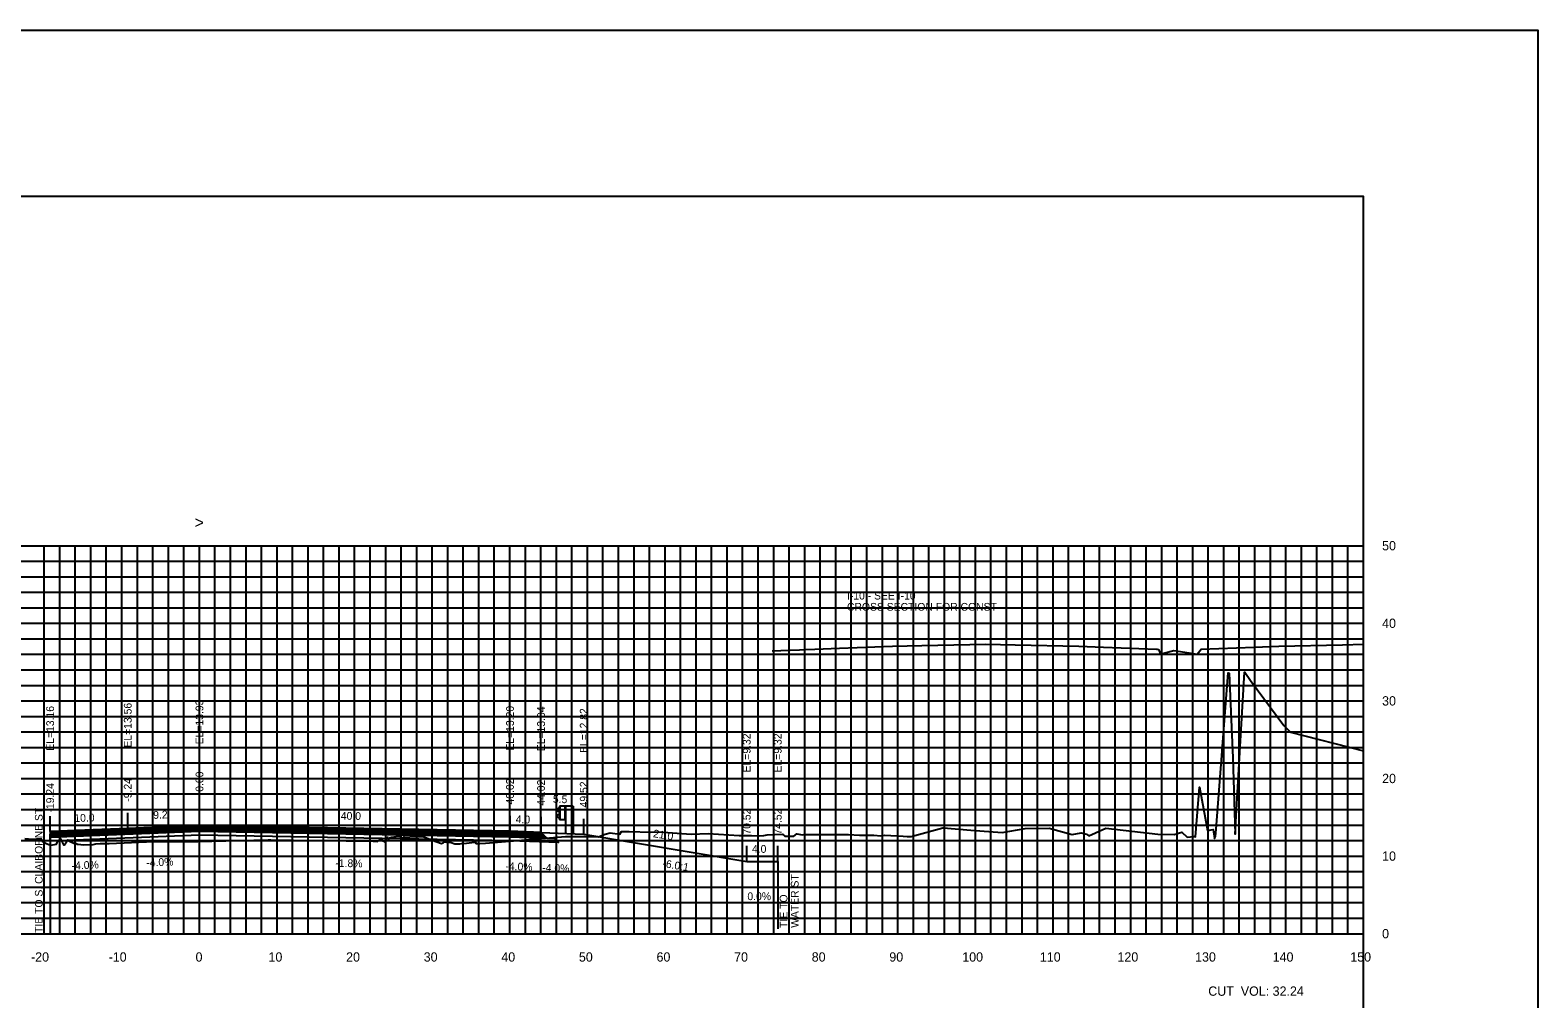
# Model space of a CAD drawing. Extents: x 1797518 to 1804843, y 248068 to 251132.
# Drawn here: x 1804649.2 to 1804843.5, y 250166 to 250290.9 of the extents above; entities that cross this region are included whole.
import ezdxf

# ---------------------------------------------------------------- set-up
doc = ezdxf.new("R2010")
doc.units = 0
for name, color, linetype in [('1', 7, 'Continuous'), ('10', 7, 'Continuous'), ('3', 7, 'Continuous'), ('31', 7, 'Continuous'), ('4', 7, 'Continuous'), ('60', 7, 'Continuous'), ('ANNO-TXT', 7, 'Continuous'), ('BASE', 7, 'Continuous'), ('CL-CNST', 7, 'Continuous'), ('Level 1', 7, 'Continuous'), ('Level 62', 7, 'Continuous'), ('LOWER BINDER', 7, 'Continuous'), ('M-ROADS', 7, 'Continuous'), ('UPPER BINDER', 7, 'Continuous'), ('WEARING', 7, 'Continuous')]:
    doc.layers.add(name, color=color, linetype=linetype)

msp = doc.modelspace()

# ---------------------------------------------------------------- linework, layer by layer
for p, q in [((1804651.76, 250187.59), (1804651.76, 250189.59)), ((1804661.76, 250187.99), (1804661.76, 250189.99)), ((1804671, 250188.36), (1804671, 250190.36)), ((1804711.02, 250187.63), (1804711.02, 250189.63)), ((1804715.02, 250187.47), (1804715.02, 250189.47)), ((1804720.52, 250187.25), (1804720.52, 250189.25)), ((1804741.52, 250183.75), (1804741.52, 250185.75)), ((1804745.52, 250183.75), (1804745.52, 250185.75))]:
    msp.add_line(p, q)
msp.add_lwpolyline([(1804521, 250079.43), (1804821, 250079.43), (1804821, 250269.43), (1804521, 250269.43)], close=True)
at = {"layer": '1'}
msp.add_lwpolyline([(1804501.93, 250290.86), (1804843.47, 250290.86), (1804843.47, 250044.2), (1804501.93, 250044.2)], close=True, dxfattribs=at)
at = {"layer": '3'}
for p, q in [((1804651.76, 250187.7), (1804651.76, 250174.43)), ((1804745.52, 250183.75), (1804745.52, 250175.05))]:
    msp.add_line(p, q, dxfattribs=at)
at = {"layer": '60'}
for p, q in [((1804821, 250174.43), (1804821, 250224.43)), ((1804821.06, 250224.43), (1804821, 250224.43)), ((1804821.06, 250214.43), (1804821, 250214.43)), ((1804821.06, 250204.43), (1804821, 250204.43)), ((1804821.06, 250194.43), (1804821, 250194.43)), ((1804821.06, 250184.43), (1804821, 250184.43)), ((1804521, 250174.43), (1804821, 250174.43)), ((1804651, 250174.37), (1804651, 250174.43)), ((1804661, 250174.37), (1804661, 250174.43)), ((1804671, 250174.37), (1804671, 250174.43)), ((1804681, 250174.37), (1804681, 250174.43)), ((1804691, 250174.37), (1804691, 250174.43)), ((1804701, 250174.37), (1804701, 250174.43)), ((1804711, 250174.37), (1804711, 250174.43)), ((1804721, 250174.37), (1804721, 250174.43)), ((1804731, 250174.37), (1804731, 250174.43)), ((1804741, 250174.37), (1804741, 250174.43)), ((1804751, 250174.37), (1804751, 250174.43)), ((1804761, 250174.37), (1804761, 250174.43)), ((1804771, 250174.37), (1804771, 250174.43)), ((1804781, 250174.37), (1804781, 250174.43)), ((1804791, 250174.37), (1804791, 250174.43)), ((1804801, 250174.37), (1804801, 250174.43)), ((1804811, 250174.37), (1804811, 250174.43)), ((1804821, 250174.37), (1804821, 250174.43)), ((1804821.06, 250174.43), (1804821, 250174.43))]:
    msp.add_line(p, q, dxfattribs=at)
at = {"layer": 'BASE'}
msp.add_lwpolyline([(1804651.76, 250186.87), (1804671, 250187.64), (1804711.02, 250186.91), (1804715.77, 250186.72), (1804716.77, 250186.68), (1804717.29, 250186.16), (1804711.02, 250186.41), (1804671, 250187.14), (1804651.76, 250186.37)], close=True, dxfattribs=at)
at = {"layer": 'CL-CNST'}
for points in [[(1804744.82, 250210.86), (1804745.93, 250210.91), (1804748.32, 250211), (1804748.95, 250211.03), (1804750.32, 250211.08), (1804753.48, 250211.21), (1804760.32, 250211.48), (1804764.11, 250211.56), (1804772.32, 250211.75), (1804776.12, 250211.66), (1804784.32, 250211.48), (1804787.49, 250211.35), (1804794.32, 250211.08), (1804794.4, 250211.08), (1804794.57, 250211.07), (1804794.66, 250210.88), (1804794.86, 250210.47), (1804795.4, 250210.61), (1804796.57, 250210.94), (1804798.53, 250210.61), (1804799.55, 250210.47), (1804799.92, 250210.89), (1804800.1, 250211.08), (1804806.93, 250211.35), (1804810.1, 250211.48), (1804818.29, 250211.66), (1804821, 250211.72)], [(1804651.76, 250187.59), (1804661.76, 250187.99), (1804671, 250188.36), (1804711.02, 250187.63), (1804715.02, 250187.47), (1804720.52, 250187.25), (1804741.52, 250183.75), (1804745.52, 250183.75)]]:
    msp.add_lwpolyline(points, dxfattribs=at)
at = {"layer": 'Level 1'}
for p, q in [((1804717.4, 250190.72), (1804717.04, 250190.42)), ((1804717.4, 250190.87), (1804717.4, 250189.12)), ((1804719.15, 250190.87), (1804717.4, 250190.87)), ((1804717.45, 250190.87), (1804717.45, 250189.12)), ((1804718.1, 250190.87), (1804718.1, 250189.12)), ((1804718.15, 250190.87), (1804718.15, 250187.34)), ((1804719.15, 250190.87), (1804719.15, 250187.3)), ((1804717.04, 250190.35), (1804717.4, 250190.06)), ((1804717.4, 250189.92), (1804717.04, 250189.62)), ((1804717.04, 250189.55), (1804717.4, 250189.27)), ((1804718.15, 250189.12), (1804717.4, 250189.12))]:
    msp.add_line(p, q, dxfattribs=at)
for centre in [(1804717.07, 250190.38), (1804717.07, 250189.59)]:
    msp.add_arc(centre, 0.05, 135, 226.6208, dxfattribs=at)
at = {"layer": 'Level 62'}
for p, q in [((1804521, 250224.43), (1804821, 250224.43)), ((1804651, 250174.43), (1804651, 250224.43)), ((1804653, 250174.43), (1804653, 250224.43)), ((1804655, 250174.43), (1804655, 250224.43)), ((1804657, 250174.43), (1804657, 250224.43)), ((1804659, 250174.43), (1804659, 250224.43)), ((1804661, 250174.43), (1804661, 250224.43)), ((1804663, 250174.43), (1804663, 250224.43)), ((1804665, 250174.43), (1804665, 250224.43)), ((1804667, 250174.43), (1804667, 250224.43)), ((1804669, 250174.43), (1804669, 250224.43)), ((1804671, 250174.43), (1804671, 250224.43)), ((1804673, 250174.43), (1804673, 250224.43)), ((1804675, 250174.43), (1804675, 250224.43)), ((1804677, 250174.43), (1804677, 250224.43)), ((1804679, 250174.43), (1804679, 250224.43)), ((1804681, 250174.43), (1804681, 250224.43)), ((1804683, 250174.43), (1804683, 250224.43)), ((1804685, 250174.43), (1804685, 250224.43)), ((1804687, 250174.43), (1804687, 250224.43)), ((1804689, 250174.43), (1804689, 250224.43)), ((1804691, 250174.43), (1804691, 250224.43)), ((1804693, 250174.43), (1804693, 250224.43)), ((1804695, 250174.43), (1804695, 250224.43)), ((1804697, 250174.43), (1804697, 250224.43)), ((1804699, 250174.43), (1804699, 250224.43)), ((1804701, 250174.43), (1804701, 250224.43)), ((1804703, 250174.43), (1804703, 250224.43)), ((1804705, 250174.43), (1804705, 250224.43)), ((1804707, 250174.43), (1804707, 250224.43)), ((1804709, 250174.43), (1804709, 250224.43)), ((1804711, 250174.43), (1804711, 250224.43)), ((1804713, 250174.43), (1804713, 250224.43)), ((1804715, 250174.43), (1804715, 250224.43)), ((1804717, 250174.43), (1804717, 250224.43)), ((1804719, 250174.43), (1804719, 250224.43)), ((1804721, 250174.43), (1804721, 250224.43)), ((1804723, 250174.43), (1804723, 250224.43)), ((1804725, 250174.43), (1804725, 250224.43)), ((1804727, 250174.43), (1804727, 250224.43)), ((1804729, 250174.43), (1804729, 250224.43)), ((1804731, 250174.43), (1804731, 250224.43)), ((1804733, 250174.43), (1804733, 250224.43)), ((1804735, 250174.43), (1804735, 250224.43)), ((1804737, 250174.43), (1804737, 250224.43)), ((1804739, 250174.43), (1804739, 250224.43)), ((1804741, 250174.43), (1804741, 250224.43)), ((1804743, 250174.43), (1804743, 250224.43)), ((1804745, 250174.43), (1804745, 250224.43)), ((1804747, 250174.43), (1804747, 250224.43)), ((1804749, 250174.43), (1804749, 250224.43)), ((1804751, 250174.43), (1804751, 250224.43)), ((1804753, 250174.43), (1804753, 250224.43)), ((1804755, 250174.43), (1804755, 250224.43)), ((1804757, 250174.43), (1804757, 250224.43)), ((1804759, 250174.43), (1804759, 250224.43)), ((1804761, 250174.43), (1804761, 250224.43)), ((1804763, 250174.43), (1804763, 250224.43)), ((1804765, 250174.43), (1804765, 250224.43)), ((1804767, 250174.43), (1804767, 250224.43)), ((1804769, 250174.43), (1804769, 250224.43)), ((1804771, 250174.43), (1804771, 250224.43)), ((1804773, 250174.43), (1804773, 250224.43)), ((1804775, 250174.43), (1804775, 250224.43)), ((1804777, 250174.43), (1804777, 250224.43)), ((1804779, 250174.43), (1804779, 250224.43)), ((1804781, 250174.43), (1804781, 250224.43)), ((1804783, 250174.43), (1804783, 250224.43)), ((1804785, 250174.43), (1804785, 250224.43)), ((1804787, 250174.43), (1804787, 250224.43)), ((1804789, 250174.43), (1804789, 250224.43)), ((1804791, 250174.43), (1804791, 250224.43)), ((1804793, 250174.43), (1804793, 250224.43)), ((1804795, 250174.43), (1804795, 250224.43)), ((1804797, 250174.43), (1804797, 250224.43)), ((1804799, 250174.43), (1804799, 250224.43)), ((1804801, 250174.43), (1804801, 250224.43)), ((1804803, 250174.43), (1804803, 250224.43)), ((1804805, 250174.43), (1804805, 250224.43)), ((1804807, 250174.43), (1804807, 250224.43)), ((1804809, 250174.43), (1804809, 250224.43)), ((1804811, 250174.43), (1804811, 250224.43)), ((1804813, 250174.43), (1804813, 250224.43)), ((1804815, 250174.43), (1804815, 250224.43)), ((1804817, 250174.43), (1804817, 250224.43)), ((1804819, 250174.43), (1804819, 250224.43)), ((1804821, 250174.43), (1804821, 250224.43)), ((1804521, 250222.43), (1804821, 250222.43)), ((1804521, 250220.43), (1804821, 250220.43)), ((1804521, 250218.43), (1804821, 250218.43)), ((1804521, 250216.43), (1804821, 250216.43)), ((1804521, 250214.43), (1804821, 250214.43)), ((1804521, 250212.43), (1804821, 250212.43)), ((1804521, 250210.43), (1804821, 250210.43)), ((1804521, 250208.43), (1804821, 250208.43)), ((1804521, 250206.43), (1804821, 250206.43)), ((1804521, 250204.43), (1804821, 250204.43)), ((1804521, 250202.43), (1804821, 250202.43)), ((1804521, 250200.43), (1804821, 250200.43)), ((1804521, 250198.43), (1804821, 250198.43)), ((1804521, 250196.43), (1804821, 250196.43)), ((1804521, 250194.43), (1804821, 250194.43)), ((1804521, 250192.43), (1804821, 250192.43)), ((1804521, 250190.43), (1804821, 250190.43)), ((1804521, 250188.43), (1804821, 250188.43)), ((1804521, 250186.43), (1804821, 250186.43)), ((1804521, 250184.43), (1804821, 250184.43)), ((1804521, 250182.43), (1804821, 250182.43)), ((1804521, 250180.43), (1804821, 250180.43)), ((1804521, 250178.43), (1804821, 250178.43)), ((1804521, 250176.43), (1804821, 250176.43)), ((1804521, 250174.43), (1804821, 250174.43))]:
    msp.add_line(p, q, dxfattribs=at)
at = {"layer": 'LOWER BINDER'}
for points in [[(1804671, 250188.02), (1804711.02, 250187.29), (1804715.38, 250187.11), (1804715.57, 250186.92), (1804711.02, 250187.1), (1804671, 250187.83), (1804651.76, 250187.06), (1804651.76, 250187.25)], [(1804671, 250187.83), (1804711.02, 250187.1), (1804715.57, 250186.92), (1804715.77, 250186.72), (1804711.02, 250186.91), (1804671, 250187.64), (1804651.76, 250186.87), (1804651.76, 250187.06)]]:
    msp.add_lwpolyline(points, close=True, dxfattribs=at)
at = {"layer": 'M-ROADS'}
msp.add_lwpolyline([(1804648.52, 250186.71), (1804649.46, 250186.62), (1804650.56, 250186.71), (1804650.74, 250186.33), (1804651.15, 250186.11), (1804651.8, 250185.84), (1804651.82, 250185.82), (1804652.59, 250185.97), (1804652.75, 250186.34), (1804652.92, 250186.46), (1804653.09, 250186.69), (1804653.11, 250186.65), (1804653.48, 250185.89), (1804653.56, 250185.89), (1804653.63, 250185.88), (1804654.06, 250186.52), (1804654.17, 250186.4), (1804655, 250186.02), (1804655.09, 250186.04), (1804655.14, 250186.03), (1804655.2, 250185.96), (1804655.36, 250185.95), (1804656.08, 250185.9), (1804657.3, 250185.92), (1804657.64, 250185.99), (1804658.21, 250186.04), (1804659.36, 250186.07), (1804665.14, 250186.3), (1804665.44, 250186.31), (1804667.36, 250186.29), (1804667.61, 250186.3), (1804668.02, 250186.31), (1804670.25, 250186.31), (1804670.39, 250186.31), (1804670.8, 250186.32), (1804678.02, 250186.47), (1804679.86, 250186.51), (1804680.22, 250186.51), (1804680.59, 250186.48), (1804682.9, 250186.49), (1804682.97, 250186.49), (1804683.12, 250186.49), (1804689.91, 250186.4), (1804690.96, 250186.41), (1804692.34, 250186.4), (1804692.41, 250186.4), (1804692.6, 250186.39), (1804693.37, 250186.35), (1804693.96, 250186.29), (1804694.42, 250186.68), (1804694.67, 250186.36), (1804694.86, 250186.4), (1804694.87, 250186.39), (1804694.88, 250186.36), (1804694.88, 250186.24), (1804694.88, 250186.27), (1804694.89, 250186.4), (1804694.89, 250186.45), (1804694.96, 250186.37), (1804695.11, 250186.72), (1804695.26, 250186.86), (1804695.27, 250186.86), (1804695.36, 250186.53), (1804695.51, 250186.8), (1804695.59, 250186.79), (1804695.59, 250186.82), (1804695.67, 250186.82), (1804695.76, 250186.85), (1804696.08, 250186.91), (1804696.34, 250186.95), (1804696.54, 250186.98), (1804696.86, 250186.99), (1804696.92, 250186.77), (1804697.13, 250186.7), (1804697.37, 250186.91), (1804697.46, 250186.87), (1804698.77, 250186.95), (1804699.84, 250186.94), (1804700.97, 250186.47), (1804702.21, 250186.05), (1804702.44, 250186.18), (1804702.58, 250186.28), (1804702.6, 250186.25), (1804702.84, 250186.21), (1804703.44, 250186.16), (1804703.89, 250186.02), (1804703.96, 250186.02), (1804704.28, 250186.02), (1804704.55, 250186.02), (1804704.79, 250186.04), (1804705.41, 250186.09), (1804706.45, 250186.23), (1804706.49, 250186.24), (1804706.5, 250186.29), (1804706.52, 250186.25), (1804706.64, 250186.06), (1804707.1, 250186.03), (1804707.13, 250186.05), (1804707.86, 250186.08), (1804718.19, 250186.94), (1804718.42, 250186.94), (1804720.43, 250186.94), (1804720.73, 250186.94), (1804722.43, 250186.9), (1804722.49, 250186.94), (1804723.3, 250187.25), (1804723.91, 250187.42), (1804725.19, 250187.26), (1804725.39, 250187.59), (1804726.37, 250187.59), (1804729.16, 250187.52), (1804730.18, 250187.54), (1804731.35, 250187.47), (1804734.36, 250187.26), (1804736.54, 250187.32), (1804740.53, 250187.1), (1804742.14, 250187.09), (1804743.16, 250187.06), (1804743.71, 250187.09), (1804744.16, 250187.16), (1804746.13, 250187.24), (1804746.44, 250186.99), (1804747.6, 250186.98), (1804748, 250187.31), (1804748.69, 250187.18), (1804748.89, 250187.19), (1804754.62, 250187.21), (1804756.06, 250187.13), (1804757.91, 250187.13), (1804758.8, 250187.04), (1804759.3, 250187.13), (1804761.67, 250187), (1804762.22, 250186.94), (1804762.72, 250186.94), (1804766.8, 250188.07), (1804766.86, 250188.08), (1804766.86, 250188.08), (1804766.87, 250188.08), (1804770.39, 250187.79), (1804774.42, 250187.48), (1804777.41, 250187.98), (1804780.49, 250188.03), (1804783.48, 250187.19), (1804784.63, 250187.41), (1804785.3, 250187.27), (1804785.63, 250187.05), (1804787.81, 250188.03), (1804794.49, 250187.27), (1804796.61, 250187.2), (1804797.61, 250187.49), (1804798.27, 250186.86), (1804799.16, 250186.95), (1804799.37, 250186.9), (1804799.88, 250193.29), (1804800.89, 250187.73), (1804801.65, 250187.87), (1804801.79, 250186.69), (1804801.94, 250186.95), (1804802.02, 250187.89), (1804803.55, 250208.04), (1804803.68, 250208.01), (1804804.15, 250197.08), (1804804.46, 250187.27), (1804804.73, 250191.91), (1804805.66, 250208.12), (1804805.71, 250208.11), (1804806.43, 250207.07), (1804810.75, 250201.24), (1804811.59, 250200.38), (1804821, 250198.01)], dxfattribs=at)
at = {"layer": 'UPPER BINDER'}
msp.add_lwpolyline([(1804715.38, 250187.11), (1804715.18, 250187.31), (1804711.02, 250187.48), (1804671, 250188.21), (1804651.76, 250187.44), (1804651.76, 250187.25), (1804671, 250188.02), (1804711.02, 250187.29)], close=True, dxfattribs=at)
at = {"layer": 'WEARING'}
msp.add_lwpolyline([(1804715.18, 250187.31), (1804715.02, 250187.47), (1804711.02, 250187.63), (1804671, 250188.36), (1804661.76, 250187.99), (1804651.76, 250187.59), (1804651.76, 250187.44), (1804671, 250188.21), (1804711.02, 250187.48)], close=True, dxfattribs=at)

# ---------------------------------------------------------------- texts
msp.add_text('-6.0:1', height=1, rotation=350.5377).set_placement((1804730.61, 250183.03))
at = {"layer": '10'}
for s, p in [('-20', (1804649.3, 250170.83)), ('-10', (1804659.3, 250170.83)), ('0', (1804670.5, 250170.83)), ('10', (1804679.9, 250170.83)), ('20', (1804689.9, 250170.83)), ('30', (1804699.9, 250170.83)), ('40', (1804709.9, 250170.83)), ('50', (1804719.9, 250170.83)), ('60', (1804729.9, 250170.83)), ('70', (1804739.9, 250170.83)), ('80', (1804749.9, 250170.83)), ('90', (1804759.9, 250170.83)), ('100', (1804769.3, 250170.83)), ('110', (1804779.3, 250170.83)), ('120', (1804789.3, 250170.83)), ('130', (1804799.3, 250170.83)), ('140', (1804809.3, 250170.83)), ('150', (1804819.3, 250170.83))]:
    msp.add_text(s, height=1.2, dxfattribs=at).set_placement(p)
at = {"layer": '3'}
for s, p in [('I-10 - SEE I-10', (1804754.44, 250217.49)), ('CROSS SECTION FOR CONST ', (1804754.44, 250216.05))]:
    msp.add_text(s, height=1, dxfattribs=at).set_placement(p)
for s, p in [('EL=13.56', (1804662.26, 250198.41)), ('EL=13.93', (1804671.5, 250198.83)), ('EL=13.16', (1804652.26, 250198.01)), ('EL=13.20', (1804711.52, 250198.02)), ('EL=13.04', (1804715.52, 250197.94)), ('EL=12.82', (1804721.02, 250197.72)), ('EL=9.32', (1804742.02, 250195.21)), ('EL=9.32', (1804746.02, 250195.21)), ('-9.24', (1804662.26, 250191.44)), ('0.00', (1804671.5, 250192.72)), ('40.02', (1804711.52, 250191.08)), ('-19.24', (1804652.26, 250190.04)), ('44.02', (1804715.52, 250190.92)), ('49.52', (1804721.02, 250190.7)), ('TIE TO S. CLAIBORNE ST', (1804650.8, 250174.53)), ('70.52', (1804742.02, 250187.2)), ('74.52', (1804746.02, 250187.2)), ('WATER ST', (1804748.21, 250175.18)), ('TIE TO', (1804746.77, 250175.18))]:
    msp.add_text(s, height=1, rotation=90, dxfattribs=at).set_placement(p)
at = {"layer": '31'}
for s, p in [('50', (1804823.4, 250223.83)), ('40', (1804823.4, 250213.83)), ('30', (1804823.4, 250203.83)), ('20', (1804823.4, 250193.83)), ('10', (1804823.4, 250183.83)), ('0', (1804823.4, 250173.83))]:
    msp.add_text(s, height=1.2, dxfattribs=at).set_placement(p)
at = {"layer": '4'}
for s, rotation, p in [('5.5', 357.7094, (1804716.53, 250191.31)), ('10.0', 2.2906, (1804654.9, 250188.81)), ('9.2', 2.2906, (1804665.06, 250189.22)), ('40.0', 358.9551, (1804689.21, 250189.13)), ('4.0', 357.7094, (1804711.74, 250188.7)), ('21.0', 350.5377, (1804729.41, 250186.88)), ('-4.0%', 2.2906, (1804654.55, 250182.7)), ('-4.0%', 2.2906, (1804664.17, 250183.08)), ('-1.8%', 358.9551, (1804688.51, 250183.04)), ('-4.0%', 357.7094, (1804710.41, 250182.65)), ('-4.0%', 357.7094, (1804715.16, 250182.46))]:
    msp.add_text(s, height=1, rotation=rotation, dxfattribs=at).set_placement(p)
for s, p in [('4.0', (1804742.2, 250184.85)), ('0.0%', (1804741.61, 250178.75))]:
    msp.add_text(s, height=1, dxfattribs=at).set_placement(p)
at = {"layer": '60'}
msp.add_text('>', height=1.5, dxfattribs=at).set_placement((1804670.39, 250226.68))
at = {"layer": 'ANNO-TXT'}
msp.add_text('CUT  VOL: 32.24', height=1.2, dxfattribs=at).set_placement((1804801, 250166.43))

doc.saveas('drawing.dxf')
